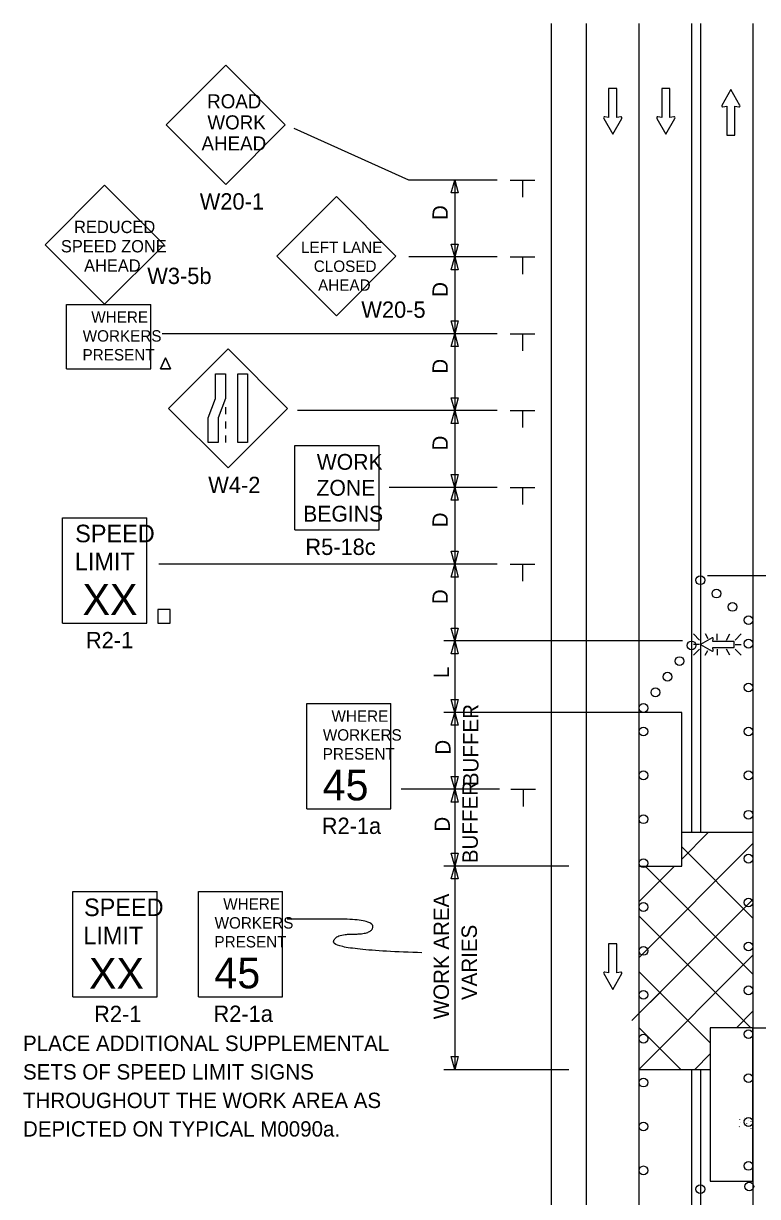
# Model space of a CAD drawing. Extents: x 16729 to 18475, y 5932 to 6920.
# Drawn here: x 16729 to 17064, y 6382 to 6916 of the extents above; entities that cross this region are included whole.
import ezdxf

# ---------------------------------------------------------------- set-up
doc = ezdxf.new("R2010")
doc.units = 0
for name, color, linetype in [('ALI_LEGAL_EX', 7, 'Continuous'), ('MT_SCRATCH_LEVEL_A', 7, 'Continuous'), ('MT_SCRATCH_LEVEL_E', 7, 'Continuous'), ('PAVT_EDGE_EX', 7, 'Continuous'), ('TRAFFIC_SIGNS_PR', 7, 'Continuous'), ('TYPICAL_TEXT_DIMEN_PR', 7, 'Continuous')]:
    doc.layers.add(name, color=color, linetype=linetype)

msp = doc.modelspace()

# ---------------------------------------------------------------- linework, layer by layer
at = {"layer": 'ALI_LEGAL_EX'}
for p, q in [((17010.12, 6916.46), (17010.12, 6065.34)), ((17062.12, 6916.46), (17062.12, 6065.34))]:
    msp.add_line(p, q, dxfattribs=at)
for points in [[(17010.12, 6916.46), (17010.12, 6891.46)], [(17062.12, 6916.46), (17062.12, 6891.46)], [(17010.12, 6816.46), (17010.12, 6791.46)], [(17062.12, 6816.46), (17062.12, 6791.46)], [(17010.12, 6716.46), (17010.12, 6691.46)], [(17062.12, 6716.46), (17062.12, 6691.46)], [(17062.12, 6616.46), (17062.12, 6591.46)], [(17010.12, 6516.46), (17010.12, 6491.46)], [(17062.12, 6498.5), (17062.12, 6473.5)], [(17010.12, 6416.46), (17010.12, 6391.46)]]:
    msp.add_lwpolyline(points, dxfattribs=at)
at = {"layer": 'MT_SCRATCH_LEVEL_A'}
msp.add_line((17010.12, 6439.88), (17042.62, 6439.88), dxfattribs=at)
at = {"layer": 'MT_SCRATCH_LEVEL_E'}
for p, q in [((17000.04, 6886.83), (16996.3, 6886.83)), ((16996.3, 6886.83), (16996.3, 6873.57)), ((17000.04, 6886.83), (16996.3, 6886.83)), ((16996.3, 6886.83), (16996.3, 6873.57)), ((17000.04, 6873.57), (17000.04, 6886.83)), ((17000.04, 6873.57), (17000.04, 6886.83)), ((17024.27, 6886.83), (17020.53, 6886.83)), ((17020.53, 6886.83), (17020.53, 6873.57)), ((17024.27, 6886.83), (17020.53, 6886.83)), ((17020.53, 6886.83), (17020.53, 6873.57)), ((17024.27, 6873.57), (17024.27, 6886.83)), ((17024.27, 6873.57), (17024.27, 6886.83)), ((17052.03, 6886.4), (17047.92, 6879.15)), ((17052.03, 6886.4), (17047.92, 6879.15)), ((17056.18, 6879.15), (17052.03, 6886.4)), ((17056.18, 6879.15), (17052.03, 6886.4)), ((16996.3, 6873.57), (16994.52, 6873.89)), ((16996.3, 6873.57), (16994.52, 6873.89)), ((17001.82, 6873.89), (17000.04, 6873.57)), ((17001.82, 6873.89), (17000.04, 6873.57)), ((17020.53, 6873.57), (17018.75, 6873.89)), ((17020.53, 6873.57), (17018.75, 6873.89)), ((17026.05, 6873.89), (17024.27, 6873.57)), ((17026.05, 6873.89), (17024.27, 6873.57)), ((17048.4, 6878.47), (17050.18, 6878.79)), ((17048.4, 6878.47), (17050.18, 6878.79)), ((17050.18, 6878.79), (17050.18, 6865.53)), ((17050.18, 6878.79), (17050.18, 6865.53)), ((17053.92, 6865.53), (17053.92, 6878.79)), ((17053.92, 6878.79), (17055.7, 6878.47)), ((17053.92, 6865.53), (17053.92, 6878.79)), ((17053.92, 6878.79), (17055.7, 6878.47)), ((16994.04, 6873.2), (16998.19, 6865.96)), ((16994.04, 6873.2), (16998.19, 6865.96)), ((16998.19, 6865.96), (17002.3, 6873.2)), ((16998.19, 6865.96), (17002.3, 6873.2)), ((17018.27, 6873.2), (17022.42, 6865.96)), ((17018.27, 6873.2), (17022.42, 6865.96)), ((17022.42, 6865.96), (17026.53, 6873.2)), ((17022.42, 6865.96), (17026.53, 6873.2)), ((17050.18, 6865.53), (17053.92, 6865.53)), ((17050.18, 6865.53), (17053.92, 6865.53)), ((17000.04, 6497.13), (16996.3, 6497.13)), ((16996.3, 6497.13), (16996.3, 6483.88)), ((17000.04, 6497.13), (16996.3, 6497.13)), ((16996.3, 6497.13), (16996.3, 6483.88)), ((17000.04, 6483.88), (17000.04, 6497.13)), ((17000.04, 6483.88), (17000.04, 6497.13)), ((16996.3, 6483.88), (16994.52, 6484.19)), ((16996.3, 6483.88), (16994.52, 6484.19)), ((17001.82, 6484.19), (17000.04, 6483.88)), ((17001.82, 6484.19), (17000.04, 6483.88)), ((16994.04, 6483.51), (16998.19, 6476.27)), ((16994.04, 6483.51), (16998.19, 6476.27)), ((16998.19, 6476.27), (17002.3, 6483.51)), ((16998.19, 6476.27), (17002.3, 6483.51))]:
    msp.add_line(p, q, dxfattribs=at)
for centre, start, end in [((17048.33, 6878.93), 150.4248, 279.9638), ((17048.33, 6878.93), 150.4248, 279.9638), ((17055.77, 6878.93), 260.0362, 29.7731), ((17055.77, 6878.93), 260.0362, 29.7731), ((16994.45, 6873.43), 80.0362, 209.7731), ((16994.45, 6873.43), 80.0362, 209.7731), ((17001.89, 6873.43), 330.4248, 99.9638), ((17001.89, 6873.43), 330.4248, 99.9638), ((17018.68, 6873.43), 80.0362, 209.7731), ((17018.68, 6873.43), 80.0362, 209.7731), ((17026.12, 6873.43), 330.4248, 99.9638), ((17026.12, 6873.43), 330.4248, 99.9638), ((16994.45, 6483.73), 80.0362, 209.7731), ((16994.45, 6483.73), 80.0362, 209.7731), ((17001.89, 6483.73), 330.4248, 99.9638), ((17001.89, 6483.73), 330.4248, 99.9638)]:
    msp.add_arc(centre, 0.463, start, end, dxfattribs=at)
at = {"layer": 'PAVT_EDGE_EX'}
for p, q in [((16970.12, 6916.46), (16970.12, 6065.34)), ((16986.12, 6916.46), (16986.12, 6065.34)), ((17034.12, 6916.46), (17034.12, 6547.86)), ((17038.12, 6916.46), (17038.12, 6547.86)), ((17062.12, 6547.86), (17029.36, 6547.86)), ((17029.62, 6535.74), (17041.74, 6547.86)), ((17010.12, 6490.79), (17062.12, 6542.79)), ((17062.12, 6508.79), (17029.62, 6541.29)), ((17010.12, 6516.24), (17026.41, 6532.54)), ((17062.12, 6483.34), (17012.92, 6532.54)), ((17006.94, 6462.15), (17062.12, 6517.33)), ((17061.1, 6458.9), (17010.12, 6509.88)), ((17010.12, 6439.88), (17062.12, 6491.88)), ((17042.62, 6451.92), (17010.12, 6484.42)), ((17010.12, 6465.33), (17020.06, 6475.27)), ((17054.6, 6458.9), (17062.12, 6466.42)), ((17029.21, 6439.88), (17010.12, 6458.97)), ((17035.58, 6439.88), (17042.62, 6446.92)), ((17034.12, 6439.88), (17034.12, 6065.34)), ((17038.12, 6439.88), (17038.12, 6065.34)), ((17056.11, 6417.1), (17056.17, 6417.22)), ((17056.3, 6415.9), (17056.35, 6415.83)), ((17058.04, 6417.97), (17058.09, 6417.9)), ((17058.08, 6416.57), (17058.13, 6416.69)), ((17059.26, 6415.07), (17059.31, 6415.19)), ((17059.88, 6416.82), (17059.93, 6416.75)), ((17061.16, 6416.25), (17061.17, 6416.13)), ((17055.89, 6413.8), (17055.94, 6413.73)), ((17061.28, 6412.87), (17061.33, 6412.99)), ((17062.04, 6413.83), (17062.1, 6413.76))]:
    msp.add_line(p, q, dxfattribs=at)
for points in [[(17029.62, 6602.54), (17010.12, 6602.54), (17010.12, 6532.54), (17029.62, 6532.54)], [(17062.12, 6458.9), (17042.62, 6458.9), (17042.62, 6388.9), (17062.12, 6388.9)]]:
    msp.add_lwpolyline(points, close=True, dxfattribs=at)
at = {"layer": 'TRAFFIC_SIGNS_PR'}
for p, q in [((16821.69, 6897.41), (16794.54, 6870.26)), ((16848.84, 6870.26), (16821.69, 6897.41)), ((16794.54, 6870.26), (16821.69, 6843.1)), ((16821.69, 6843.1), (16848.84, 6870.26)), ((16766.49, 6842.79), (16739.34, 6815.64)), ((16793.65, 6815.64), (16766.49, 6842.79)), ((16872.15, 6837.6), (16844.99, 6810.45)), ((16899.3, 6810.45), (16872.15, 6837.6)), ((16739.34, 6815.64), (16766.49, 6788.49)), ((16766.49, 6788.49), (16793.65, 6815.64)), ((16844.99, 6810.45), (16872.15, 6783.29)), ((16872.15, 6783.29), (16899.3, 6810.45)), ((16749.1, 6788.41), (16787.5, 6788.41)), ((16749.1, 6759.09), (16749.1, 6788.41)), ((16787.5, 6759.09), (16787.5, 6788.41)), ((16822.78, 6768.22), (16795.63, 6741.07)), ((16849.93, 6741.07), (16822.78, 6768.22)), ((16749.1, 6759.09), (16787.5, 6759.09)), ((16795.63, 6741.07), (16822.78, 6713.91)), ((16821.53, 6741.56), (16821.53, 6738.36)), ((16822.78, 6713.91), (16849.93, 6741.07)), ((16821.53, 6735.16), (16821.53, 6731.96)), ((16821.53, 6728.76), (16821.53, 6725.56)), ((16853.21, 6685.72), (16853.21, 6724.12)), ((16853.21, 6724.12), (16891.61, 6724.12)), ((16891.61, 6685.72), (16891.61, 6724.12)), ((16747.29, 6691.21), (16785.69, 6691.21)), ((16747.29, 6643.21), (16747.29, 6691.21)), ((16785.69, 6643.21), (16785.69, 6691.21)), ((16853.21, 6685.72), (16891.61, 6685.72)), ((16747.29, 6643.21), (16785.69, 6643.21)), ((17034.94, 6638.3), (17037.76, 6635.48)), ((17037.76, 6633.45), (17034.94, 6633.45)), ((17041.66, 6636.12), (17040.4, 6638.3)), ((17045.85, 6635.48), (17045.85, 6638.3)), ((17049.98, 6635.48), (17051.61, 6638.3)), ((17053.93, 6635.48), (17056.75, 6638.3)), ((17053.93, 6633.45), (17056.75, 6633.45)), ((17034.94, 6628.6), (17037.76, 6631.42)), ((17040.38, 6628.6), (17041.58, 6630.69)), ((17045.85, 6631.42), (17045.85, 6628.6)), ((17051.63, 6628.6), (17050.01, 6631.42)), ((17053.93, 6631.42), (17056.75, 6628.6)), ((16858.63, 6606.6), (16897.03, 6606.6)), ((16858.63, 6558.6), (16858.63, 6606.6)), ((16897.03, 6558.6), (16897.03, 6606.6)), ((16858.63, 6558.6), (16897.03, 6558.6)), ((16809.26, 6520.97), (16847.66, 6520.97)), ((16809.26, 6472.97), (16809.26, 6520.97)), ((16847.66, 6472.97), (16847.66, 6520.97)), ((16752.06, 6520.88), (16790.46, 6520.88)), ((16752.06, 6472.88), (16752.06, 6520.88)), ((16790.46, 6472.88), (16790.46, 6520.88)), ((16752.06, 6472.88), (16790.46, 6472.88)), ((16809.26, 6472.97), (16847.66, 6472.97))]:
    msp.add_line(p, q, dxfattribs=at)
for points in [[(16794.25, 6764.03), (16792.01, 6759.09)], [(16792.01, 6759.09), (16794.25, 6764.03)], [(16796.49, 6759.09), (16794.25, 6764.03)], [(16794.25, 6764.03), (16796.49, 6759.09)], [(16792.01, 6759.09), (16796.49, 6759.09)], [(16796.49, 6759.09), (16792.01, 6759.09)], [(17043.52, 6636.46), (17038.21, 6633.45), (17043.52, 6630.41)], [(17044.02, 6630.77), (17043.79, 6632.06), (17053.51, 6632.06), (17053.51, 6634.81), (17043.79, 6634.81), (17044.02, 6636.11)]]:
    msp.add_lwpolyline(points, dxfattribs=at)
for points in [[(16821.53, 6756.8), (16821.53, 6745.62), (16818.19, 6736.74), (16818.19, 6725.56), (16813.7, 6725.56), (16813.7, 6736.74), (16817.04, 6745.62), (16817.04, 6756.8)], [(16831.67, 6756.8), (16831.67, 6725.56), (16827.18, 6725.56), (16827.18, 6756.8)], [(16790.71, 6643.21), (16796.3, 6643.21), (16796.3, 6649.38), (16790.71, 6649.38)]]:
    msp.add_lwpolyline(points, close=True, dxfattribs=at)
for centre in [(17038.11, 6662.75), (17045.44, 6656.68), (17052.76, 6650.61), (17060.09, 6644.55), (17034.12, 6633.08), (17060.09, 6633.87), (17028.63, 6625.94), (17023.14, 6618.81), (17017.64, 6611.68), (17060.09, 6613.87), (17012.15, 6604.55), (17012.15, 6593.87), (17060.09, 6593.87), (17012.15, 6573.87), (17060.09, 6573.87), (17012.15, 6553.87), (17060.09, 6555.91), (17060.09, 6535.91), (17012.15, 6533.87), (17012.15, 6513.87), (17060.09, 6515.91), (17012.15, 6493.87), (17060.09, 6495.91), (17012.15, 6473.87), (17060.09, 6475.91), (17060.09, 6455.91), (17012.15, 6453.87), (17012.15, 6433.87), (17012.15, 6433.87), (17060.09, 6435.91), (17012.15, 6413.87), (17060.09, 6415.91), (17012.15, 6393.87), (17060.09, 6395.91), (17038.12, 6385.34), (17060.44, 6386.55)]:
    msp.add_circle(centre, 2, dxfattribs=at)
for centre, start, end in [((17043.68, 6636.17), 350.7308, 118.8916), ((17043.68, 6630.71), 241.4833, 9.9593)]:
    msp.add_arc(centre, 0.341, start, end, dxfattribs=at)
at = {"layer": 'TYPICAL_TEXT_DIMEN_PR'}
for p, q in [((16905.2, 6845.09), (16852.9, 6868.56)), ((16945.44, 6845.09), (16905.2, 6845.09)), ((16924.55, 6839.23), (16926.12, 6845.09)), ((16926.12, 6845.09), (16926.12, 6810.09)), ((16926.12, 6845.09), (16927.69, 6839.23)), ((16951.37, 6845.09), (16962.62, 6845.09)), ((16956.99, 6845.09), (16956.99, 6837.3)), ((16926.12, 6839.23), (16924.55, 6839.23)), ((16927.69, 6839.23), (16926.12, 6839.23)), ((16926.12, 6810.09), (16924.55, 6815.95)), ((16924.55, 6815.95), (16926.12, 6815.95)), ((16926.12, 6815.95), (16927.69, 6815.95)), ((16927.69, 6815.95), (16926.12, 6810.09)), ((16945.44, 6810.09), (16905.2, 6810.09)), ((16924.55, 6804.23), (16926.12, 6810.09)), ((16926.12, 6810.09), (16926.12, 6775.09)), ((16926.12, 6810.09), (16927.69, 6804.23)), ((16951.37, 6810.09), (16962.62, 6810.09)), ((16956.99, 6810.09), (16956.99, 6802.3)), ((16926.12, 6804.23), (16924.55, 6804.23)), ((16927.69, 6804.23), (16926.12, 6804.23)), ((16926.12, 6775.09), (16924.55, 6780.95)), ((16924.55, 6780.95), (16926.12, 6780.95)), ((16926.12, 6780.95), (16927.69, 6780.95)), ((16927.69, 6780.95), (16926.12, 6775.09)), ((16945.44, 6775.09), (16792.74, 6775.09)), ((16924.55, 6769.23), (16926.12, 6775.09)), ((16926.12, 6775.09), (16926.12, 6740.09)), ((16926.12, 6775.09), (16927.69, 6769.23)), ((16951.37, 6775.09), (16962.62, 6775.09)), ((16956.99, 6775.09), (16956.99, 6767.3)), ((16926.12, 6769.23), (16924.55, 6769.23)), ((16927.69, 6769.23), (16926.12, 6769.23)), ((16926.12, 6740.09), (16924.55, 6745.95)), ((16924.55, 6745.95), (16926.12, 6745.95)), ((16926.12, 6745.95), (16927.69, 6745.95)), ((16927.69, 6745.95), (16926.12, 6740.09)), ((16945.44, 6740.09), (16854.38, 6740.09)), ((16924.55, 6734.23), (16926.12, 6740.09)), ((16926.12, 6740.09), (16926.12, 6705.09)), ((16926.12, 6740.09), (16927.69, 6734.23)), ((16951.37, 6740.09), (16962.62, 6740.09)), ((16956.99, 6740.09), (16956.99, 6732.3)), ((16926.12, 6734.23), (16924.55, 6734.23)), ((16927.69, 6734.23), (16926.12, 6734.23)), ((16926.12, 6705.09), (16924.55, 6710.95)), ((16924.55, 6710.95), (16926.12, 6710.95)), ((16926.12, 6710.95), (16927.69, 6710.95)), ((16927.69, 6710.95), (16926.12, 6705.09)), ((16945.44, 6705.09), (16896.21, 6705.09)), ((16924.55, 6699.23), (16926.12, 6705.09)), ((16926.12, 6705.09), (16926.12, 6670.09)), ((16926.12, 6705.09), (16927.69, 6699.23)), ((16951.37, 6705.09), (16962.62, 6705.09)), ((16956.99, 6705.09), (16956.99, 6697.3)), ((16926.12, 6699.23), (16924.55, 6699.23)), ((16927.69, 6699.23), (16926.12, 6699.23)), ((16926.12, 6670.09), (16924.55, 6675.95)), ((16924.55, 6675.95), (16926.12, 6675.95)), ((16926.12, 6675.95), (16927.69, 6675.95)), ((16927.69, 6675.95), (16926.12, 6670.09)), ((16945.44, 6670.09), (16791.25, 6670.09)), ((16924.55, 6664.23), (16926.12, 6670.09)), ((16926.12, 6670.09), (16926.12, 6635.09)), ((16926.12, 6670.09), (16927.69, 6664.23)), ((16951.37, 6670.09), (16962.62, 6670.09)), ((16956.99, 6670.09), (16956.99, 6662.3)), ((16926.12, 6664.23), (16924.55, 6664.23)), ((16927.69, 6664.23), (16926.12, 6664.23)), ((17151.12, 6664.74), (17041.37, 6664.74)), ((16926.12, 6635.09), (16924.55, 6640.95)), ((16924.55, 6640.95), (16926.12, 6640.95)), ((16926.12, 6640.95), (16927.69, 6640.95)), ((16927.69, 6640.95), (16926.12, 6635.09)), ((17029.92, 6635.09), (16921.12, 6635.09)), ((16924.55, 6629.23), (16926.12, 6635.09)), ((16926.12, 6635.09), (16926.12, 6602.54)), ((16926.12, 6635.09), (16927.69, 6629.23)), ((16926.12, 6629.23), (16924.55, 6629.23)), ((16927.69, 6629.23), (16926.12, 6629.23)), ((16926.12, 6602.54), (16924.55, 6608.4)), ((16924.55, 6608.4), (16926.12, 6608.4)), ((16926.12, 6608.4), (16927.69, 6608.4)), ((16927.69, 6608.4), (16926.12, 6602.54)), ((17010.12, 6602.54), (16921.12, 6602.54)), ((16924.55, 6596.68), (16926.12, 6602.54)), ((16926.12, 6602.54), (16927.69, 6596.68)), ((16926.12, 6602.54), (16926.12, 6567.97)), ((16926.12, 6596.68), (16924.55, 6596.68)), ((16927.69, 6596.68), (16926.12, 6596.68)), ((16926.12, 6567.54), (16924.55, 6573.4)), ((16924.55, 6573.4), (16926.12, 6573.4)), ((16926.12, 6573.4), (16927.69, 6573.4)), ((16927.69, 6573.4), (16926.12, 6567.54)), ((16946.59, 6567.54), (16901.76, 6567.54)), ((16924.55, 6561.68), (16926.12, 6567.54)), ((16926.12, 6567.54), (16927.69, 6561.68)), ((16926.12, 6567.54), (16926.12, 6532.54)), ((16951.67, 6567.53), (16962.92, 6567.53)), ((16957.3, 6567.53), (16957.3, 6559.74)), ((16926.12, 6561.68), (16924.55, 6561.68)), ((16927.69, 6561.68), (16926.12, 6561.68)), ((16926.12, 6532.54), (16924.55, 6538.4)), ((16924.55, 6538.4), (16926.12, 6538.4)), ((16926.12, 6538.4), (16927.69, 6538.4)), ((16927.69, 6538.4), (16926.12, 6532.54)), ((16978.23, 6532.54), (16921.12, 6532.54)), ((16924.55, 6526.68), (16926.12, 6532.54)), ((16926.12, 6532.54), (16927.69, 6526.68)), ((16926.12, 6532.54), (16926.12, 6439.88)), ((16926.12, 6526.68), (16924.55, 6526.68)), ((16927.69, 6526.68), (16926.12, 6526.68)), ((17062.12, 6458.9), (17151.12, 6458.9)), ((16926.12, 6439.88), (16924.55, 6445.74)), ((16924.55, 6445.74), (16926.12, 6445.74)), ((16926.12, 6445.74), (16927.69, 6445.74)), ((16927.69, 6445.74), (16926.12, 6439.88)), ((16921.12, 6439.88), (16978.23, 6439.88))]:
    msp.add_line(p, q, dxfattribs=at)
msp.add_open_spline([(16911.2, 6493.03), (16870.92, 6494.27), (16870.92, 6501.52), (16888.81, 6501.52), (16888.81, 6508.38), (16855.87, 6508.38), (16849.7, 6508.38)], degree=2, dxfattribs=at)

# ---------------------------------------------------------------- texts
at = {"layer": 'TRAFFIC_SIGNS_PR'}
for s, height, p in [('ROAD', 6.4, (16813.23, 6877.79)), ('WORK', 6.4, (16813.34, 6868.19)), ('AHEAD', 6.4, (16810.65, 6858.59)), ('W20-1', 7.44, (16809.86, 6831.66)), ('REDUCED', 5.6, (16752.55, 6820.95)), ('SPEED ZONE', 5.6, (16746.54, 6812.15)), ('LEFT LANE', 5.2, (16856.03, 6811.84)), ('AHEAD', 5.6, (16757.11, 6803.35)), ('W3-5b', 7.44, (16785.93, 6797.73)), ('CLOSED', 5.2, (16861.86, 6803.24)), ('AHEAD', 5.2, (16863.81, 6794.64)), ('W20-5', 7.44, (16883.53, 6782.34)), ('WHERE', 5.2, (16760.41, 6780.09)), ('WORKERS', 5.2, (16756.49, 6771.49)), ('PRESENT', 5.2, (16756.42, 6762.89)), ('WORK', 7.217, (16863.21, 6713.09)), ('W4-2', 7.44, (16813.74, 6702.48)), ('ZONE', 7.217, (16863.09, 6701.28)), ('BEGINS', 7.217, (16857.02, 6689.47)), ('SPEED', 8, (16753.06, 6680.07)), ('R5-18c', 7.44, (16858.02, 6674.28)), ('LIMIT', 8, (16752.9, 6667.27)), ('XX', 14.031, (16756.41, 6646.97)), ('R2-1', 7.44, (16757.97, 6631.77)), ('WHERE', 5.2, (16869.94, 6598.28)), ('WORKERS', 5.2, (16866.01, 6589.68)), ('PRESENT', 5.2, (16865.94, 6581.08)), ('45', 14.031, (16865.93, 6562.45)), ('R2-1a', 7.44, (16865.48, 6547.16)), ('SPEED', 8, (16757.09, 6509.74)), ('WHERE', 5.2, (16820.57, 6512.65)), ('LIMIT', 8, (16756.76, 6496.94)), ('WORKERS', 5.2, (16816.64, 6504.05)), ('PRESENT', 5.2, (16816.57, 6495.45)), ('XX', 14.031, (16759.37, 6476.64)), ('45', 14.031, (16816.56, 6476.82)), ('R2-1', 7.44, (16761.67, 6461.44)), ('R2-1a', 7.44, (16816.11, 6461.53)), ('PLACE ADDITIONAL SUPPLEMENTAL', 7, (16729.26, 6448.27)), ('SETS OF SPEED LIMIT SIGNS', 7, (16729.26, 6435.27)), ('THROUGHOUT THE WORK AREA AS', 7, (16729.26, 6422.27)), ('DEPICTED ON TYPICAL M0090a.', 7, (16729.26, 6409.27))]:
    msp.add_text(s, height=height, dxfattribs=at).set_placement(p)
at = {"layer": 'TYPICAL_TEXT_DIMEN_PR'}
for s, p in [('D', (16922.98, 6826.88)), ('D', (16922.98, 6791.88)), ('D', (16922.98, 6756.88)), ('D', (16922.98, 6721.88)), ('D', (16922.98, 6686.88)), ('D', (16922.98, 6651.88)), ('L', (16923.56, 6618.17)), ('BUFFER', (16936.95, 6568.94)), ('D', (16924.21, 6583.29)), ('BUFFER', (16936.65, 6533.86)), ('D', (16923.91, 6548.22)), ('WORK AREA', (16923.47, 6462.72)), ('VARIES', (16936.22, 6471.45))]:
    msp.add_text(s, height=7, rotation=90, dxfattribs=at).set_placement(p)

doc.saveas('drawing.dxf')
